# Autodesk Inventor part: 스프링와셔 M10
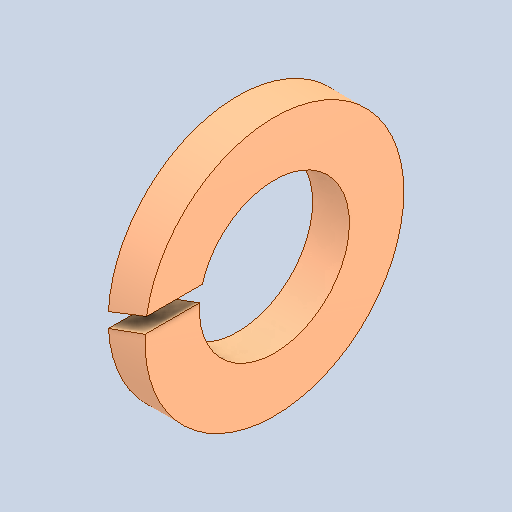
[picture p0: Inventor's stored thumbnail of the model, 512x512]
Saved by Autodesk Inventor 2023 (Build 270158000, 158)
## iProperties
Created: 2024-09
Part Number: 스프링와셔 M10
Material: 강철, 연강
Description: 스프링 잠금 와셔
Document SubType Name: Modeling
Designer: home
Density: 7.85 g/cm^3
Appearance: 기본값
Author: jhkim
Sending System: Autodesk Inventor 2025
Preprocessor: ST-DEVELOPER v20
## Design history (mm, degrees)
node "스프링와셔 M101"
node "솔리드1"
body "Solid1"
